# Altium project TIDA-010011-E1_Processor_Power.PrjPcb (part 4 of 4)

## Sheet TIDA-010011-E1_Processor_Power _Pg10.SchDoc: PMIC 3 OUTPUT
size 431 x 279 mm; Date: Not shown in title block; ApprovedBy: Not shown in title block; CheckedBy: Not shown in title block; Author: Not shown in title block; CompanyName: Not shown in title block; DrawnBy: Sreenivasa; Engineer: Not shown in title block; Organization: Not shown in title block; Address1: Not shown in title block; Address2: Not shown in title block; Address3: Not shown in title block; Address4: Not shown in title block; DocumentNumber: 1; Revision: Use project parameter SCH_Rev; SheetNumber: 10; SheetTotal: 12; PageSetup: Record=PageOptions¦CenterHorizontal=True¦CenterVertical=True¦PrintScale=0.62¦XCorrection=1.00¦YCorrection=1.00¦PrintKind=0¦BorderSize=5000000¦LeftOffset=0¦BottomOffset=0¦Orientation=2¦PaperLength=1000¦PaperWidth=1000¦Scale=100¦PaperSource=15¦PrintQuality=600¦MediaType=1¦DitherType=10¦PrintScaleMode=1¦PaperKind=Letter
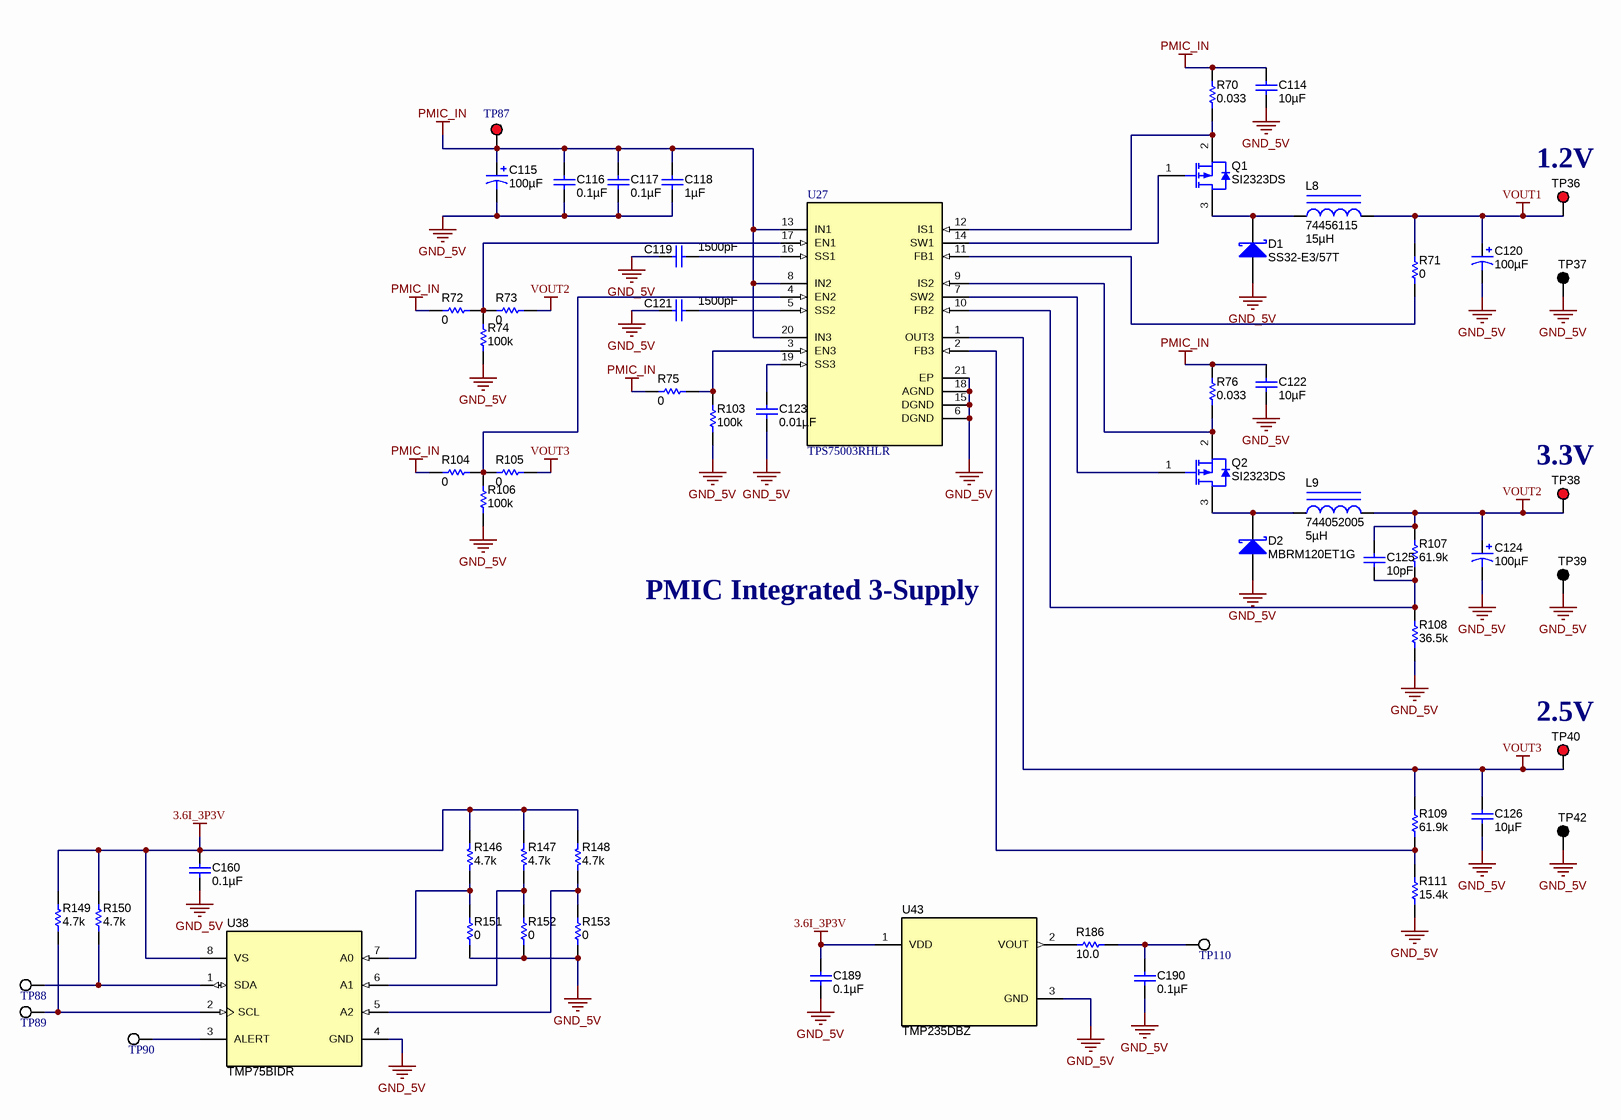
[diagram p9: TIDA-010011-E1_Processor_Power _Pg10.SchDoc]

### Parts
C114  ValueDisplayed: 10µF  [0805_HV]  (hidden comment: CGA4J1X7S1C106K125AC)
C115  ValueDisplayed: 100µF  [7343-20]  (hidden comment: 6TPE100MI)
C116  ValueDisplayed: 0.1µF  [0603]  (hidden comment: C0603C104Z4VACTU)
C117  ValueDisplayed: 0.1µF  [0603]  (hidden comment: C0603C104Z4VACTU)
C118  ValueDisplayed: 1µF  [0603]  (hidden comment: GRM185C80J105KE26D)
C119  ValueDisplayed: 1500pF  [0603]  (hidden comment: GRM188R71H152KA01D)
C120  ValueDisplayed: 100µF  [7343-20]  (hidden comment: 6TPE100MI)
C121  ValueDisplayed: 1500pF  [0603]  (hidden comment: GRM188R71H152KA01D)
C122  ValueDisplayed: 10µF  [0805_HV]  (hidden comment: CGA4J1X7S1C106K125AC)
C123  ValueDisplayed: 0.01µF  [0603]  (hidden comment: GRM188R71E103KA01D)
C124  ValueDisplayed: 100µF  [7343-20]  (hidden comment: 6TPE100MI)
C125  ValueDisplayed: 10pF  [0603]  (hidden comment: C0603C100F5GAC7867)
C126  ValueDisplayed: 10µF  [0805_HV]  (hidden comment: GRM21BR71A106KE51L)
C160  ValueDisplayed: 0.1µF  [0603]  (hidden comment: 06033C104KAT2A)
C189  ValueDisplayed: 0.1µF  [0603]  (hidden comment: 06033C104KAT2A)
C190  ValueDisplayed: 0.1µF  [0603]  (hidden comment: 06033C104KAT2A)
D1  SS32-E3/57T  [SMC]
D2  MBRM120ET1G  [POWERMITE]
L8  74456115  ValueDisplayed: 15µH  [WE-PD4-L]
L9  744052005  ValueDisplayed: 5µH  [WE-TPC-L]
Q1  SI2323DS  [SOT-23]
Q2  SI2323DS  [SOT-23]
R70  ValueDisplayed: 0.033  [1206]  (hidden comment: ERJ-8CWFR033V)
R71  ValueDisplayed: 0  [0603]  (hidden comment: ERJ-3GEY0R00V)
R72  ValueDisplayed: 0  [0603]  (hidden comment: ERJ-3GEY0R00V)
R73  ValueDisplayed: 0  [0603]  (hidden comment: ERJ-3GEY0R00V)
R74  ValueDisplayed: 100k  [0603]  (hidden comment: RC0603FR-07100KL)
R75  ValueDisplayed: 0  [0603]  (hidden comment: ERJ-3GEY0R00V)
R76  ValueDisplayed: 0.033  [1206]  (hidden comment: ERJ-8CWFR033V)
R103  ValueDisplayed: 100k  [0603]  (hidden comment: RC0603FR-07100KL)
R104  ValueDisplayed: 0  [0603]  (hidden comment: ERJ-3GEY0R00V)
R105  ValueDisplayed: 0  [0603]  (hidden comment: ERJ-3GEY0R00V)
R106  ValueDisplayed: 100k  [0603]  (hidden comment: RC0603FR-07100KL)
R107  ValueDisplayed: 61.9k  [0603]  (hidden comment: CRCW060361K9FKEA)
R108  ValueDisplayed: 36.5k  [0603]  (hidden comment: CRCW060336K5FKEA)
R109  ValueDisplayed: 61.9k  [0603]  (hidden comment: CRCW060361K9FKEA)
R111  ValueDisplayed: 15.4k  [0603]  (hidden comment: CRCW060315K4FKEA)
R146  ValueDisplayed: 4.7k  [0603]  (hidden comment: CR0603-JW-472GLF)
R147  ValueDisplayed: 4.7k  [0603]  (hidden comment: CR0603-JW-472GLF)
R148  ValueDisplayed: 4.7k  [0603]  (hidden comment: CR0603-JW-472GLF)
R149  ValueDisplayed: 4.7k  [0603]  (hidden comment: CR0603-JW-472GLF)
R150  ValueDisplayed: 4.7k  [0603]  (hidden comment: CR0603-JW-472GLF)
R151  ValueDisplayed: 0  [0603]  (hidden comment: CRCW06030000Z0EA)
R152  ValueDisplayed: 0  [0603]  (hidden comment: CRCW06030000Z0EA)
R153  ValueDisplayed: 0  [0603]  (hidden comment: CRCW06030000Z0EA)
R186  ValueDisplayed: 10.0  [0603]  (hidden comment: CRCW060310R0FKEAHP)
TP36  5000  [Keystone5000]  (value not drawn)
TP37  5001  [Keystone5001]  (value not drawn)
TP38  5000  [Keystone5000]  (value not drawn)
TP39  5001  [Keystone5001]  (value not drawn)
TP40  5000  [Keystone5000]  (value not drawn)
TP42  5001  [Keystone5001]  (value not drawn)
TP87  5000  [Keystone5000]  (value not drawn)
TP88  5002  [Keystone5002]  (value not drawn)
TP89  5002  [Keystone5002]  (value not drawn)
TP90  5002  [Keystone5002]  (value not drawn)
TP110  5002  [Keystone5002]  (value not drawn)
U27  TPS75003RHLR  [RHL0020A]
U38  TMP75BIDR  [D0008A_N]
U43  TMP235DBZ  [DBZ0003A_N]

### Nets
3.6I_3P3V: C160.2 C189.2 R146.2 R147.2 R148.2 R149.2 R150.2 U38.8(VS) U43.1(VDD)
GND_5V: C114.2 C115.2(-) C116.2 C117.2 C118.2 C119.2 C120.2(-) C121.2 C122.2 C123.2 C124.2(-) C126.2 C160.1 C189.1 C190.1 D1.2(A) D2.2(A) R74.2 R103.2 R106.2 R108.1 R111.1 R151.2 R152.2 R153.2 TP37.1 TP39.1 TP42.1 U27.6(DGND) U27.15(DGND) U27.18(AGND) U27.21(EP) U38.4(GND) U43.3(GND)
PMIC_IN: C114.1 C115.1(+) C116.1 C117.1 C118.1 C122.1 R70.1 R72.2 R75.2 R76.1 R104.2 TP87.1 U27.8(IN2) U27.13(IN1) U27.20(IN3)
VOUT1: C120.1(+) L8.2 R71.1 TP36.1
VOUT2: C124.1(+) C125.1 L9.2 R73.1 R107.2 TP38.1
VOUT3: C126.1 R105.1 R109.2 TP40.1 U27.1(OUT3)
NetC119_1: C119.1 U27.16(SS1)
NetC121_1: C121.1 U27.5(SS2)
NetC123_1: C123.1 U27.19(SS3)
NetC125_2: C125.2 R107.1 R108.2 U27.10(FB2)
NetC190_2: C190.2 R186.1 TP110.1
NetD1_1: D1.1(K) L8.1 Q1.3(D)
NetD2_1: D2.1(K) L9.1 Q2.3(D)
NetQ1_1: Q1.1(G) U27.14(SW1)
NetQ1_2: Q1.2(S) R70.2 U27.12(IS1)
NetQ2_1: Q2.1(G) U27.7(SW2)
NetQ2_2: Q2.2(S) R76.2 U27.9(IS2)
NetR71_2: R71.2 U27.11(FB1)
NetR72_1: R72.1 R73.2 R74.1 U27.17(EN1)
NetR75_1: R75.1 R103.1 U27.3(EN3)
NetR104_1: R104.1 R105.2 R106.1 U27.4(EN2)
NetR109_1: R109.1 R111.2 U27.2(FB3)
NetR146_1: R146.1 R151.1 U38.7(A0)
NetR147_1: R147.1 R152.1 U38.6(A1)
NetR148_1: R148.1 R153.1 U38.5(A2)
NetR149_1: R149.1 TP89.1 U38.2(SCL)
NetR150_1: R150.1 TP88.1 U38.1(SDA)
NetR186_2: R186.2 U43.2(VOUT)
NetTP90_1: TP90.1 U38.3(ALERT)

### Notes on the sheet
- (near TP36) 1.2V
- (near TP38) 3.3V
- PMIC Integrated 3-Supply
- (near TP40) 2.5V

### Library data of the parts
C114 C122 = CGA4J1X7S1C106K125AC: CAP, CERM, 10 µF, 16 V,+/- 10%, X7S, AEC-Q200 Grade 1, 0805; Manufacturer: TDK; Polarized: N; CompType: Capacitor; Value: 10uF; U/M: EA; Cap_F: 0.00001; Tolerance_%: 10; VDC_V: 16; Value2: 16V; TaMin_C: -55; TaMax_C: 125; Cap_Case: 0805; SizeArea_mm2: 2.5; SizeAreaWB_mm2: 6.75; SizeX_mm: 2; SizeY_mm: 1.25; SizeZ_mm: 1.45; AEC Category: Q200; AEC Qualified: Y; AEC Grade: 1
C115 C120 C124 = 6TPE100MI: CAP, Tantalum Polymer, 100 µF, 6.3 V,+/- 20%, 0.018 ohm, 7343-20 SMD; Manufacturer: Panasonic; Polarized: Y; CompType: Capacitor; Value: 100uF; U/M: EA; Cap_F: 0.0001; Tolerance_%: 20; VDC_V: 6.3; Value2: 6.3V; ESR_ohm: 0.018; IRMS_A: 2.8; TaMin_C: -55; TaMax_C: 105; Cap_Case: D; SizeAreaWB_mm2: 58.59; SizeArea_mm2: 31.39; SizeX_mm: 7.3; SizeY_mm: 4.3; SizeZ_mm: 2; AEC Category: Q200; AEC Qualified: N
C116 C117 = C0603C104Z4VACTU: CAP, CERM, 0.1 µF, 16 V,+80/-20%, Y5V, 0603; Manufacturer: Kemet; Polarized: N; CompType: Capacitor; Value: 0.1uF; U/M: EA; Cap_F: 0.0000001; Tolerance_%: 80; VDC_V: 16; Value2: 16V; TaMin_C: -30; TaMax_C: 85; SizeArea_mm2: 1.28; SizeAreaWB_mm2: 4.68; SizeX_mm: 1.6; SizeY_mm: 0.8; SizeZ_mm: 1; AEC Category: Q200; Green_Lifecycle: Not Set; Green_REACh: Incomplete
C118 = GRM185C80J105KE26D: CAP, CERM, 1 µF, 6.3 V,+/- 10%, X6S, 0603; Manufacturer: MuRata; Polarized: N; CompType: Capacitor; Value: 1uF; U/M: EA; Cap_F: 0.000001; Tolerance_%: 10; VDC_V: 6.3; Value2: 6.3V; TaMin_C: -55; TaMax_C: 105; SizeArea_mm2: 1.28; SizeAreaWB_mm2: 4.68; SizeX_mm: 1.6; SizeY_mm: 0.8; SizeZ_mm: 1; AEC Category: Q200; Green_Lifecycle: Active; Green_REACh: Passed
C119 C121 = GRM188R71H152KA01D: CAP, CERM, 1500 pF, 50 V,+/- 10%, X7R, 0603; Manufacturer: MuRata; Polarized: N; CompType: Capacitor; Value: 1500pF; U/M: EA; Cap_F: 0.0000000015; Tolerance_%: 10; VDC_V: 50; Value2: 50V; TaMin_C: -55; TaMax_C: 125; SizeArea_mm2: 1.28; SizeAreaWB_mm2: 4.68; SizeX_mm: 1.6; SizeY_mm: 0.8; SizeZ_mm: 1; AEC Category: Q200; Green_Lifecycle: Active; Green_REACh: Passed
C123 = GRM188R71E103KA01D: CAP, CERM, 0.01 µF, 25 V,+/- 10%, X7R, 0603; Manufacturer: MuRata; Polarized: N; CompType: Capacitor; Value: 0.01uF; U/M: EA; Cap_F: 0.00000001; Tolerance_%: 10; VDC_V: 25; Value2: 25V; TaMin_C: -55; TaMax_C: 125; SizeArea_mm2: 1.28; SizeAreaWB_mm2: 4.68; SizeX_mm: 1.6; SizeY_mm: 0.8; SizeZ_mm: 1; AEC Category: Q200; Green_Lifecycle: Active; Green_REACh: Passed
C125 = C0603C100F5GAC7867: CAP, CERM, 10 pF, 50 V,+/- 1%, C0G/NP0, 0603; Manufacturer: Kemet; Polarized: N; CompType: Capacitor; Value: 10pF; U/M: EA; Cap_F: 0.00000000001; Tolerance_%: 1; VDC_V: 50; Value2: 50V; TaMin_C: -55; TaMax_C: 125; SizeArea_mm2: 1.28; SizeAreaWB_mm2: 4.68; SizeX_mm: 1.6; SizeY_mm: 0.8; AEC Category: Q200; Green_Lifecycle: Active; Green_REACh: Passed
C126 = GRM21BR71A106KE51L: CAP, CERM, 10 µF, 10 V, +/- 10%, X7R, 0805; Manufacturer: MuRata; Polarized: N; CompType: Capacitor; Value: 10uF; U/M: EA; Cap_F: 0.00001; Tolerance_%: 10; ESR_ohm: 0.003; Value1: 0.003 ohm; Value2: 10V; TaMin_C: -55; TaMax_C: 125; Cap_Case: 0805; SizeArea_mm2: 2.5; SizeAreaWB_mm2: 6.75; SizeX_mm: 2; SizeY_mm: 1.25; SizeZ_mm: 1.45; AEC Category: Q200
C160 C189 C190 = 06033C104KAT2A: CAP, CERM, 0.1 µF, 25 V,+/- 10%, X7R, 0603; Manufacturer: AVX; Polarized: N; CompType: Capacitor; Value: 0.1uF; U/M: EA; Cap_F: 0.0000001; Tolerance_%: 10; ESR_ohm: 0.05; Value1: 0.05 ohm; VDC_V: 25; Value2: 25V; TaMin_C: -55; TaMax_C: 125; AEC Category: Q200; SizeArea_mm2: 1.28; SizeAreaWB_mm2: 4.68; SizeX_mm: 1.6; SizeY_mm: 0.8; SizeZ_mm: 1; Green_Lifecycle: Active; Green_REACh: Passed
D1 = SS32-E3/57T: Diode, Schottky, 20 V, 3 A, SMC; Manufacturer: Vishay-Semiconductor; U/M: EA; Vf_V: 0.5; Value: 20V; Value1: 3A; Value2: 0.5V; Io_A: 3; Vr_V: 20; TJmax_C: 125; RJC_CperW: 17; SizeAreaWB_mm2: 83.2686; SizeArea_mm2: 50.5686; SizeX_mm: 8.13; SizeY_mm: 6.22; SizeZ_mm: 2.6; AEC Category: Q101; Green_Lifecycle: Not Set; Green_REACh: Incomplete
D2 = MBRM120ET1G: Diode, Schottky, 20 V, 1 A, POWERMITE; Manufacturer: ON Semiconductor; U/M: EA; Vf_V: 0.53; Value: 20V; Value1: 1A; Value2: 0.53V; Io_A: 1; Vr_V: 20; SizeAreaWB_mm2: 14.945; SizeArea_mm2: 7.995; SizeX_mm: 3.9; SizeY_mm: 2.05; SizeZ_mm: 1.15; AEC Category: Q101; Green_Lifecycle: Active; Green_REACh: Passed
L8 = 74456115: Inductor, Drum Core, Ferrite, 15uH, 2.9A, 0.0432 ohm, SMD; Manufacturer: Wurth Elektronik eiSos; Ind_H: 15.0E-6; Imax_A: 2.9; Irms: 2.9A @ 40C rise; Isat: 3.6A @ 10% inductance drop; DCR_ohm: 0.0432; U/M: EA
L9 = 744052005: Inductor, Shielded Drum Core, Ferrite, 5uH, 1.65A, 0.047 ohm, SMD; Manufacturer: Wurth Elektronik eiSos; Ind_H: 5.0E-6; Imax_A: 1.65; Irms: 1.65A @ 30C rise; Isat: 1.8A @ 35% inductance drop; DCR_ohm: 0.047; U/M: EA
Q1 Q2 = CMP-0000092-2: MOSFET, P-CH, -20 V, -3.7 A, SOT-23; Alternate Manufacturer: None; Manufacturer: Vishay-Siliconix; SizeZ_mm: 1.1; ChType: P; Value2: 12.5 nC; Value1: 0.03; VdsMax_V: -20V; SizeX_mm: 2.5; SizeAreaWB_mm2: 14; SizeY_mm: 3; Vgs_V: -8V; QgTyp_nC: 12.5; Value: -20V; Rdson45_ohm: 0.031; SizeArea_mm2: 7.5; AEC Category: Q101; IdsMax_A: -3.7A; U/M: EA
R70 R76 = ERJ-8CWFR033V: RES, 0.033, 1%, 1 W, AEC-Q200 Grade 0, 1206; Manufacturer: Panasonic; CompType: Resistor; Value: 0.033; Value_Code: R033; Tolerance_%: 1; Value2: 1W; TempCo: 50 ppm/C; SizeArea_mm2: 5.12; SizeX_mm: 3.2; SizeY_mm: 1.6; SizeZ_mm: 1.35; EIA_Code: E96; U/M: EA; AEC Category: Q200; AEC Qualified: Y; AEC Grade: 0; Green_Lifecycle: Not Set; Green_REACh: Incomplete
R71-R73 R75 R104 R105 = ERJ-3GEY0R00V: RES, 0, 5%, 0.1 W, 0603; Manufacturer: Panasonic; CompType: Resistor; Value: 0; Value_Code: 0000; Tolerance_%: 5; Power_W: 0.1; Value2: 0.1W; VDC_V: 50; TempCo: 600 ppm/C; SizeArea_mm2: 1.28; SizeX_mm: 1.6; SizeY_mm: 0.8; SizeZ_mm: 1; EIA_Code: E24; U/M: EA; AEC Category: Q200; Green_Lifecycle: Active; Green_REACh: Passed
R74 R103 R106 = RC0603FR-07100KL: RES, 100 k, 1%, 0.1 W, 0603; Manufacturer: Yageo America; CompType: Resistor; Value: 100k; Res_ohm: 100000; Tolerance_%: 1; Power_W: 0.1; Value2: 0.1W; VDC_V: 150; TempCo: 200 ppm/C; SizeArea_mm2: 1.28; SizeX_mm: 1.6; SizeY_mm: 0.8; EIA_Code: E96; U/M: EA; AEC Category: Q200; Green_Lifecycle: Active; Green_REACh: Passed
R107 R109 = CRCW060361K9FKEA: RES, 61.9 k, 1%, 0.1 W, 0603; Manufacturer: Vishay-Dale; CompType: Resistor; Value: 61.9k; Res_ohm: 61900; Value_Code: 61k9; Tolerance_%: 1; Power_W: 0.1; Value2: 0.1W; VDC_V: 75; TempCo: 100 ppm/C; SizeArea_mm2: 1.28; SizeX_mm: 1.6; SizeY_mm: 0.8; EIA_Code: E96; U/M: EA; AEC Category: Q200; Green_Lifecycle: Active; Green_REACh: Passed
R108 = CRCW060336K5FKEA: RES, 36.5 k, 1%, 0.1 W, 0603; Manufacturer: Vishay-Dale; CompType: Resistor; Value: 36.5k; Res_ohm: 36500; Value_Code: 36k5; Tolerance_%: 1; Power_W: 0.1; Value2: 0.1W; VDC_V: 75; TempCo: 100 ppm/C; SizeArea_mm2: 1.28; SizeX_mm: 1.6; SizeY_mm: 0.8; EIA_Code: E96; U/M: EA; AEC Category: Q200; Green_Lifecycle: Active; Green_REACh: Passed
R111 = CRCW060315K4FKEA: RES, 15.4 k, 1%, 0.1 W, 0603; Manufacturer: Vishay-Dale; CompType: Resistor; Value: 15.4k; Res_ohm: 15400; Value_Code: 15k4; Tolerance_%: 1; Power_W: 0.1; Value2: 0.1W; VDC_V: 75; TempCo: 100 ppm/C; SizeArea_mm2: 1.28; SizeX_mm: 1.6; SizeY_mm: 0.8; EIA_Code: E96; U/M: EA; AEC Category: Q200; Green_Lifecycle: Active; Green_REACh: Passed
R146-R150 = CR0603-JW-472GLF: RES, 4.7 k, 5%, 0.1 W, 0603; Manufacturer: Bourns; CompType: Resistor; Value: 4.7k; Res_ohm: 4700; Value_Code: 4k70; Tolerance_%: 5; Power_W: 0.1; Value2: 0.1W; VDC_V: 50; TempCo: 200 ppm/C; EIA_Code: E24; U/M: EA; AEC Category: Q200; AEC Qualified: N; SizeArea_mm2: 1.28; SizeX_mm: 1.6; SizeY_mm: 0.8; SizeZ_mm: 1; Green_Lifecycle: Active; Green_REACh: Passed
R151-R153 = CRCW06030000Z0EA: RES, 0, 5%, 0.1 W, 0603; Manufacturer: Vishay-Dale; CompType: Resistor; Value: 0; Value_Code: 0000; Tolerance_%: 5; Power_W: 0.1; Value2: 0.1W; VDC_V: 75; TempCo: 200 ppm/C; EIA_Code: E24; U/M: EA; AEC Category: Q200; SizeArea_mm2: 1.28; SizeX_mm: 1.6; SizeY_mm: 0.8; SizeZ_mm: 1; Green_Lifecycle: Active; Green_REACh: Passed
R186 = CRCW060310R0FKEAHP: RES, 10.0, 1%, 0.25 W, 0603; Manufacturer: Vishay-Dale; CompType: Resistor; Value: 10.0; Res_ohm: 10; Value_Code: 10R0; Tolerance_%: 1; Power_W: 0.25; Value2: 0.25W; VDC_V: 75; TempCo: 100 ppm/C; SizeArea_mm2: 1.28; SizeX_mm: 1.6; SizeY_mm: 0.8; EIA_Code: E96; U/M: EA; AEC Category: Q200; Green_Lifecycle: Active; Green_REACh: Passed
TP36 TP38 TP40 = 5000: Test Point, Miniature, Red, TH; Manufacturer: Keystone; CompType: Test Point Loop; U/M: EA
TP37 TP39 TP42 = 5001: Test Point, Miniature, Black, TH; Manufacturer: Keystone; CompType: Test Point Loop; U/M: EA
TP87 = 5000: Test Point, Miniature, Red, TH; Manufacturer: Keystone; CompType: Test Point Loop; ContactFinish: Silver; Green_Lifecycle: Active; Green_REACh: Passed
TP88-TP90 TP110 = 5002: Test Point, Miniature, White, TH; Manufacturer: Keystone; CompType: Test Point Loop; ContactFinish: Silver; Green_Lifecycle: Active; Green_REACh: Passed
U27 = CMP-0037564-2: Integrated Triple Supply Power Management IC for Xilinx (R) Spartan (TM)-3 FPGAs, 2.2 to 6.5 V, -40 to 85 degC, 20-pin QFN (RHL), Green (RoHS & no Sb/Br); Manufacturer: Texas Instruments; SubFamily: DC/DC Controller (External Switch); Vin(Min)(V): 2.2; Vin(Max)(V): 6.5; Topology: Multi-Channel; Regulated Outputs(#): 3
U38 = TMP75BIDR: 1.4V-Capable Temperature Sensor with I2C/SMBus Interface in LM75 Form Factor & Pinout, D0008A (SOIC-8); Manufacturer: Texas Instruments; SymbolCreator: a0411947; SizeArea_mm2: 30.38; SizeAreaWB_mm2: 56.58; SizeX_mm: 4.9; SizeY_mm: 6.2; SizeZ_mm: 1.75; CompType: IC; U/M: EA
U43 = CMP-0013240-2: TMP235DBZ, DBZ0003A (SOP-3); Manufacturer: Texas Instruments; SizeX_mm: 2.5; SizeY_mm: 3; CompType: IC; SizeZ_mm: 1.12; SizeArea_mm2: 7.5; SizeAreaWB_mm2: 14; U/M: EA

## Sheet TIDA-010011-E1_Processor_Power _Pg11.SchDoc: PMIC AM335X
size 431 x 279 mm; Date: Not shown in title block; ApprovedBy: Not shown in title block; CheckedBy: Not shown in title block; Author: Not shown in title block; CompanyName: Not shown in title block; Engineer: Not shown in title block; Organization: Not shown in title block; Address1: Not shown in title block; Address2: Not shown in title block; Address3: Not shown in title block; Address4: Not shown in title block; DocumentNumber: 1; Revision: Use project parameter SCH_Rev; SheetNumber: 11; SheetTotal: 12; PageSetup: Record=PageOptions¦CenterHorizontal=True¦CenterVertical=True¦PrintScale=1.00¦XCorrection=1.00¦YCorrection=1.00¦PrintKind=0¦BorderSize=5000000¦LeftOffset=0¦BottomOffset=0¦Orientation=2¦PaperLength=1000¦PaperWidth=1000¦Scale=100¦PaperSource=15¦PrintQuality=600¦MediaType=1¦DitherType=10¦PaperKind=Letter¦PrintScaleMode=1
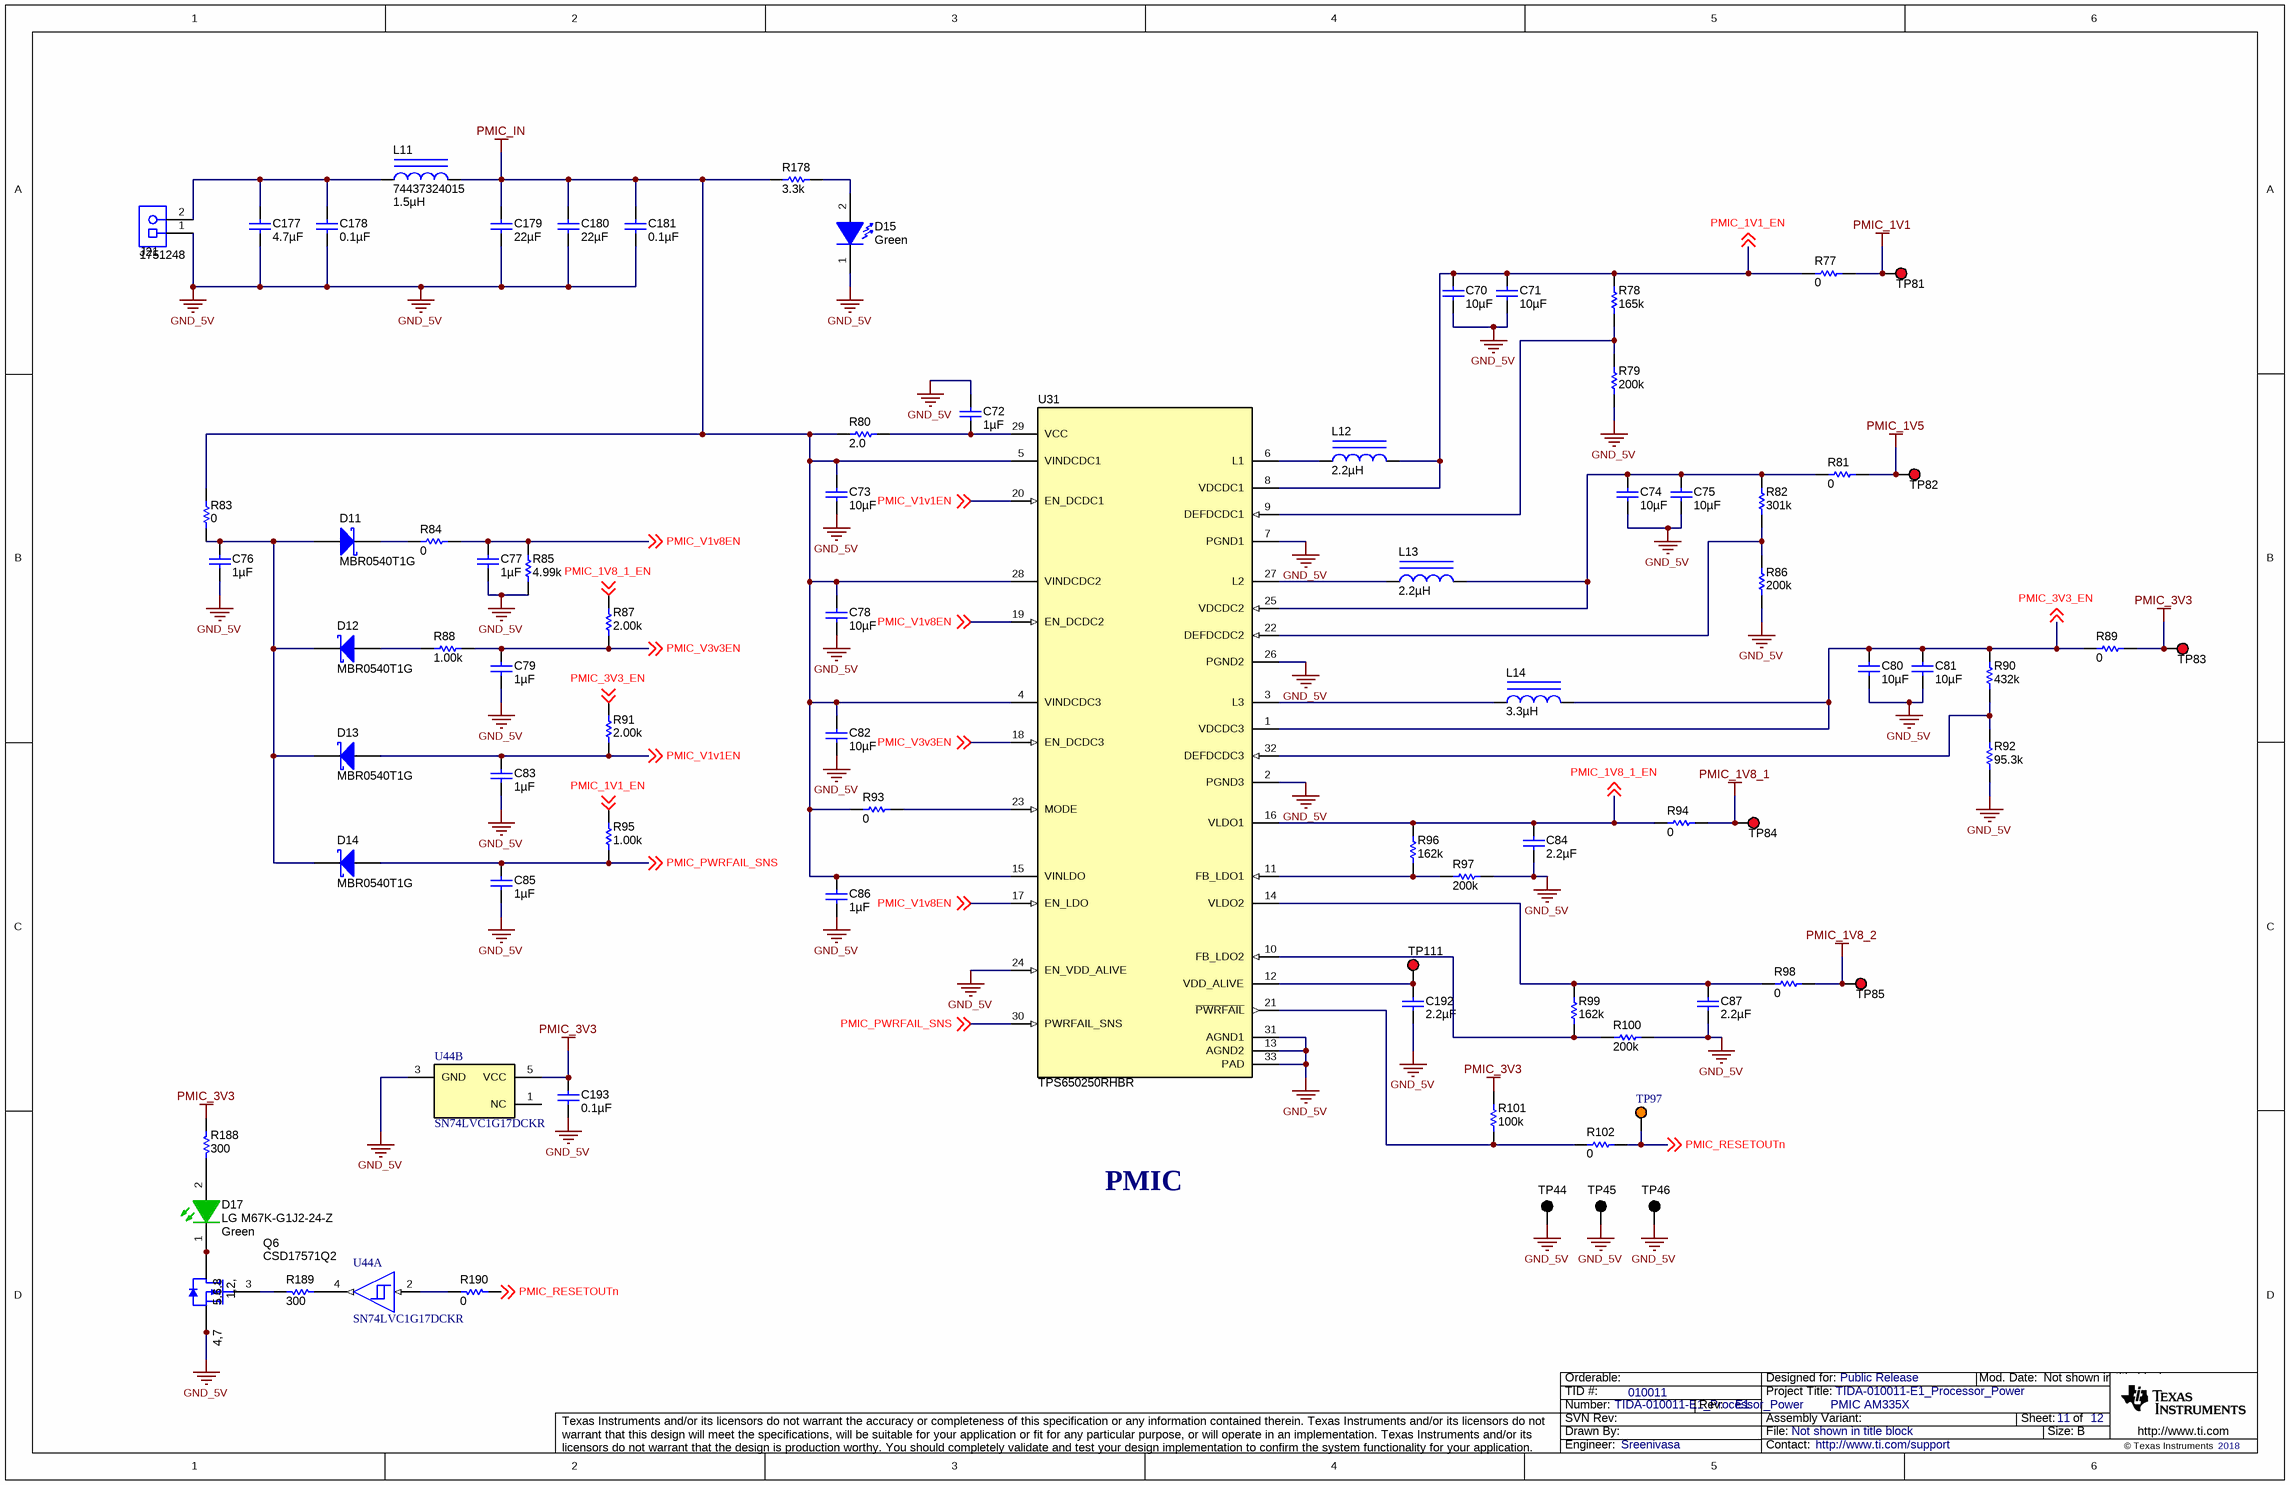
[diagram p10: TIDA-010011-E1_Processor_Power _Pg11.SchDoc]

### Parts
C70  ValueDisplayed: 10µF  [0603]  (hidden comment: C1608X5R1E106M080AC)
C71  ValueDisplayed: 10µF  [0603]  (hidden comment: C1608X5R1E106M080AC)
C72  ValueDisplayed: 1µF  [0603]  (hidden comment: C1608X7R1C105K080AC)
C73  ValueDisplayed: 10µF  [0603]  (hidden comment: C1608X5R1E106M080AC)
C74  ValueDisplayed: 10µF  [0603]  (hidden comment: C1608X5R1E106M080AC)
C75  ValueDisplayed: 10µF  [0603]  (hidden comment: C1608X5R1E106M080AC)
C76  ValueDisplayed: 1µF  [0603]  (hidden comment: C1608X7R1C105K080AC)
C77  ValueDisplayed: 1µF  [0603]  (hidden comment: C1608X7R1C105K080AC)
C78  ValueDisplayed: 10µF  [0603]  (hidden comment: C1608X5R1E106M080AC)
C79  ValueDisplayed: 1µF  [0603]  (hidden comment: C1608X7R1C105K080AC)
C80  ValueDisplayed: 10µF  [0603]  (hidden comment: C1608X5R1E106M080AC)
C81  ValueDisplayed: 10µF  [0603]  (hidden comment: C1608X5R1E106M080AC)
C82  ValueDisplayed: 10µF  [0603]  (hidden comment: C1608X5R1E106M080AC)
C83  ValueDisplayed: 1µF  [0603]  (hidden comment: C1608X7R1C105K080AC)
C84  ValueDisplayed: 2.2µF  [0603]  (hidden comment: GRM188R71A225KE15D)
C85  ValueDisplayed: 1µF  [0603]  (hidden comment: C1608X7R1C105K080AC)
C86  ValueDisplayed: 1µF  [0603]  (hidden comment: C1608X7R1C105K080AC)
C87  ValueDisplayed: 2.2µF  [0603]  (hidden comment: GRM188R71A225KE15D)
C177  ValueDisplayed: 4.7µF  [0603]  (hidden comment: GRM188R61C475KAAJ)
C178  ValueDisplayed: 0.1µF  [0603]  (hidden comment: GRM188R71C104KA01D)
C179  ValueDisplayed: 22µF  [0603]  (hidden comment: GRM188R61A226ME15D)
C180  ValueDisplayed: 22µF  [0603]  (hidden comment: GRM188R61A226ME15D)
C181  ValueDisplayed: 0.1µF  [0603]  (hidden comment: GRM188R71C104KA01D)
C192  ValueDisplayed: 2.2µF  [0603]  (hidden comment: GRM188R71A225KE15D)
C193  ValueDisplayed: 0.1µF  [0603]  (hidden comment: GMK107BJ104KAHT)
D11  MBR0540T1G  [SOD-123]
D12  MBR0540T1G  [SOD-123]
D13  MBR0540T1G  [SOD-123]
D14  MBR0540T1G  [SOD-123]
D15  value Green  [WL-SMCW_GREEN]  (hidden comment: 150060VS75000)
D17  LG M67K-G1J2-24-Z  value Green  [LG_M67K_Green]
J21  1751248  [CONN_1751248]
L11  74437324015  ValueDisplayed: 1.5µH  [IND_WE-LHMI-4020]
L12  ValueDisplayed: 2.2µH  [VLCF4020]  (hidden comment: VLCF4020T-2R2N1R7)
L13  ValueDisplayed: 2.2µH  [VLCF4020]  (hidden comment: VLCF4020T-2R2N1R7)
L14  ValueDisplayed: 3.3µH  [VLCF4020]  (hidden comment: VLCF4020T-3R3N1R5)
Q6  CSD17571Q2  [DQK0006C]
R77  ValueDisplayed: 0  [0402]  (hidden comment: CRCW04020000Z0ED)
R78  ValueDisplayed: 165k  [0402]  (hidden comment: CRCW0402165KFKED)
R79  ValueDisplayed: 200k  [0402]  (hidden comment: CRCW0402200KFKED)
R80  ValueDisplayed: 2.0  [0603]  (hidden comment: CRCW06032R00JNEA)
R81  ValueDisplayed: 0  [0402]  (hidden comment: CRCW04020000Z0ED)
R82  ValueDisplayed: 301k  [0402]  (hidden comment: CRCW0402301KFKED)
R83  ValueDisplayed: 0  [0402]  (hidden comment: CRCW04020000Z0ED)
R84  ValueDisplayed: 0  [0402]  (hidden comment: CRCW04020000Z0ED)
R85  ValueDisplayed: 4.99k  [0402]  (hidden comment: CRCW04024K99FKED)
R86  ValueDisplayed: 200k  [0402]  (hidden comment: CRCW0402200KFKED)
R87  ValueDisplayed: 2.00k  [0402]  (hidden comment: CRCW04022K00FKED)
R88  ValueDisplayed: 1.00k  [0402]  (hidden comment: CRCW04021K00FKED)
R89  ValueDisplayed: 0  [0402]  (hidden comment: CRCW04020000Z0ED)
R90  ValueDisplayed: 432k  [0402]  (hidden comment: CRCW0402432KFKED)
R91  ValueDisplayed: 2.00k  [0402]  (hidden comment: CRCW04022K00FKED)
R92  ValueDisplayed: 95.3k  [0402]  (hidden comment: CRCW040295K3FKED)
R93  ValueDisplayed: 0  [0402]  (hidden comment: CRCW04020000Z0ED)
R94  ValueDisplayed: 0  [0402]  (hidden comment: CRCW04020000Z0ED)
R95  ValueDisplayed: 1.00k  [0402]  (hidden comment: CRCW04021K00FKED)
R96  ValueDisplayed: 162k  [0402]  (hidden comment: CRCW0402162KFKED)
R97  ValueDisplayed: 200k  [0402]  (hidden comment: CRCW0402200KFKED)
R98  ValueDisplayed: 0  [0402]  (hidden comment: CRCW04020000Z0ED)
R99  ValueDisplayed: 162k  [0402]  (hidden comment: CRCW0402162KFKED)
R100  ValueDisplayed: 200k  [0402]  (hidden comment: CRCW0402200KFKED)
R101  ValueDisplayed: 100k  [0402]  (hidden comment: CRCW0402100KJNED)
R102  ValueDisplayed: 0  [0402]  (hidden comment: CRCW04020000Z0ED)
R178  ValueDisplayed: 3.3k  [0402L]  (hidden comment: CRCW04023K30JNED)
R188  ValueDisplayed: 300  [0603]  (hidden comment: CRCW0603300RJNEA)
R189  ValueDisplayed: 300  [0603]  (hidden comment: CRCW0603300RJNEA)
R190  ValueDisplayed: 0  [0603]  (hidden comment: RMCF0603ZT0R00)
TP44  5001  [Keystone5001]  (value not drawn)
TP45  5001  [Keystone5001]  (value not drawn)
TP46  5001  [Keystone5001]  (value not drawn)
TP81  (no value)  [Keystone5000]
TP82  (no value)  [Keystone5000]
TP83  (no value)  [Keystone5000]
TP84  (no value)  [Keystone5000]
TP85  (no value)  [Keystone5000]
TP97  5003  [Keystone5003]  (value not drawn)
TP111  (no value)  [Keystone5000]
U31  TPS650250RHBR  [RHB0032E]
U44  SN74LVC1G17DCKR  [DCK0005A_N]  (parts A,B of 2)

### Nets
GND_5V: C70.2 C71.2 C72.1 C73.2 C74.2 C75.2 C76.2 C77.2 C78.2 C79.2 C80.2 C81.2 C82.2 C83.2 C84.2 C85.2 C86.2 C87.2 C177.2 C178.2 C179.2 C180.2 C181.2 C192.2 C193.2 D15.1(K) J21.1 Q6.4(S) Q6.7(S) R79.1 R85.1 R86.1 R92.1 R97.1 R100.1 TP44.1 TP45.1 TP46.1 U31.2(PGND3) U31.7(PGND1) U31.13(AGND2) U31.24(EN_VDD_ALIVE) U31.26(PGND2) U31.31(AGND1) U31.33(PAD) U44.3(GND)
PMIC_1V1: R77.2 TP81.1
PMIC_1V5: R81.2 TP82.1
PMIC_1V8_1: R94.2 TP84.1
PMIC_1V8_2: R98.2 TP85.1
PMIC_3V3: C193.1 R89.2 R101.2 R188.2 TP83.1 U44.5(VCC)
PMIC_IN: C73.1 C78.1 C82.1 C86.1 C179.1 C180.1 C181.1 L11.2 R80.1 R83.2 R93.1 R178.2 U31.4(VINDCDC3) U31.5(VINDCDC1) U31.15(VINLDO) U31.28(VINDCDC2)
PMIC_1V1_EN: C70.1 C71.1 L12.2 R77.1 R78.2 R95.2 U31.8(VDCDC1) ; off-sheet PMIC_1V1_EN
PMIC_1V8_1_EN: C84.1 R87.2 R94.1 R96.2 U31.16(VLDO1) ; off-sheet PMIC_1V8_1_EN
PMIC_3V3_EN: C80.1 C81.1 L14.2 R89.1 R90.2 R91.2 U31.1(VDCDC3) ; off-sheet PMIC_3V3_EN
PMIC_PWRFAIL_SNS: C85.1 D14.2(A) R95.1 U31.30(PWRFAIL_SNS) ; off-sheet PMIC_PWRFAIL_SNS
PMIC_RESETOUTn: R102.2 R190.1 TP97.1 ; off-sheet PMIC_RESETOUTn
PMIC_V1v1EN: C83.1 D13.2(A) R91.1 U31.20(EN_DCDC1) ; off-sheet PMIC_V1v1EN
PMIC_V1v8EN: C77.1 R84.2 R85.2 U31.17(EN_LDO) U31.19(EN_DCDC2) ; off-sheet PMIC_V1v8EN
PMIC_V3v3EN: C79.1 R87.1 R88.2 U31.18(EN_DCDC3) ; off-sheet PMIC_V3v3EN
NetC72_2: C72.2 R80.2 U31.29(VCC)
NetC74_1: C74.1 C75.1 L13.2 R81.1 R82.2 U31.25(VDCDC2)
NetC76_1: C76.1 D11.2(A) D12.1(K) D13.1(K) D14.1(K) R83.1
NetC87_1: C87.1 R98.1 R99.2 U31.14(VLDO2)
NetC177_1: C177.1 C178.1 J21.2 L11.1
NetC192_1: C192.1 TP111.1 U31.12(VDD_ALIVE)
NetD11_1: D11.1(K) R84.1
NetD12_2: D12.2(A) R88.1
NetD15_2: D15.2(A) R178.1
NetD17_1: D17.1(K) Q6.1(D) Q6.2(D) Q6.5(D) Q6.6(D) Q6.8(D)
NetD17_2: D17.2(A) R188.1
NetL12_1: L12.1 U31.6(L1)
NetL13_1: L13.1 U31.27(L2)
NetL14_1: L14.1 U31.3(L3)
NetQ6_3: Q6.3(G) R189.1
NetR78_1: R78.1 R79.2 U31.9(DEFDCDC1)
NetR82_1: R82.1 R86.2 U31.22(DEFDCDC2)
NetR90_1: R90.1 R92.2 U31.32(DEFDCDC3)
NetR93_2: R93.2 U31.23(MODE)
NetR96_1: R96.1 R97.2 U31.11(FB_LDO1)
NetR99_1: R99.1 R100.2 U31.10(FB_LDO2)
NetR101_1: R101.1 R102.1 U31.21(~{PWRFAIL})
NetR189_2: R189.2 U44.4(Y)
NetR190_2: R190.2 U44.2(A)

Not connected (* = marked no-connect by the designer): U44 1(NC)

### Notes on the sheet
- PMIC

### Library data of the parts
C70 C71 C73-C75 C78 C80-C82 = C1608X5R1E106M080AC: CAP, CERM, 10 µF, 25 V, +/- 20%, X5R, 0603; Manufacturer: TDK; Polarized: N; CompType: Capacitor; Value: 10uF; U/M: EA; Cap_F: 0.00001; Tolerance_%: 20; Value1: Unknown; VDC_V: 25; Value2: 25V; TaMin_C: -55; TaMax_C: 85
C72 C76 C77 C79 C83 C85 C86 = C1608X7R1C105K080AC: CAP, CERM, 1 µF, 16 V,+/- 10%, X7R, 0603; Manufacturer: TDK; Polarized: N; CompType: Capacitor; Value: 1uF; U/M: EA; Cap_F: 0.000001; Tolerance_%: 10; ESR_ohm: 0.0057; Value1: 0.0057 ohm; VDC_V: 16; Value2: 16V; TaMin_C: -55; TaMax_C: 125; SizeArea_mm2: 1.28; SizeAreaWB_mm2: 4.68; SizeX_mm: 1.6; SizeY_mm: 0.8; SizeZ_mm: 1; AEC Category: Q200; Green_Lifecycle: Active; Green_REACh: Passed
C84 C87 C192 = GRM188R71A225KE15D: CAP, CERM, 2.2 µF, 10 V, +/- 10%, X7R, 0603; Manufacturer: MuRata; Polarized: N; CompType: Capacitor; Value: 2.2uF; U/M: EA; Cap_F: 0.0000022; Tolerance_%: 10; ESR_ohm: 0.009; Value1: 0.009 ohm; Value2: 10V; TaMin_C: -55; TaMax_C: 125
C177 = GRM188R61C475KAAJ: CAP, CERM, 4.7 µF, 16 V, +/- 10%, X5R, 0603; Manufacturer: MuRata; Polarized: N; CompType: Capacitor; Value: 4.7uF; U/M: EA; Cap_F: 0.0000047; Tolerance_%: 10; Value1: Unknown; VDC_V: 16; Value2: 16V; TaMin_C: -55; TaMax_C: 85; SizeArea_mm2: 1.28; SizeAreaWB_mm2: 4.68; SizeX_mm: 1.6; SizeY_mm: 0.8; SizeZ_mm: 1; AEC Category: Q200
C178 C181 = GRM188R71C104KA01D: CAP, CERM, 0.1 µF, 16 V, +/- 10%, X7R, 0603; Manufacturer: MuRata; Polarized: N; CompType: Capacitor; Value: 0.1uF; U/M: EA; Cap_F: 0.0000001; Tolerance_%: 10; Value1: Unknown; VDC_V: 16; Value2: 16V; TaMin_C: -55; TaMax_C: 125; SizeArea_mm2: 1.28; SizeAreaWB_mm2: 4.68; SizeX_mm: 1.6; SizeY_mm: 0.8; SizeZ_mm: 1; AEC Category: Q200
C179 C180 = GRM188R61A226ME15D: CAP, CERM, 22 µF, 10 V, +/- 20%, X5R, 0603; Manufacturer: MuRata; Polarized: N; CompType: Capacitor; Value: 22uF; U/M: EA; Cap_F: 0.000022; Tolerance_%: 20; Value1: Unknown; VDC_V: 10; Value2: 10V; TaMin_C: -55; TaMax_C: 85; SizeArea_mm2: 1.28; SizeAreaWB_mm2: 4.68; SizeX_mm: 1.6; SizeY_mm: 0.8; SizeZ_mm: 1; AEC Category: Q200
C193 = 06033C104JAT2A: 0.1µF ±10% 35V Ceramic Capacitor X5R 0603; Manufacturer: Taiyo Yuden; Polarized: N; Value: 0.1uF; U/M: EA; Cap_F: 0.0000001; Tolerance_%: 5; ESR_ohm: 0.05; Value1: 0.05 ohm; VDC_V: 25; Value2: 25V; TempCo: X7R; TaMin_C: -55; TaMax_C: 125; SizeArea_mm2: 1.28; SizeAreaWB_mm2: 4.68; SizeX_mm: 1.6; SizeY_mm: 0.8; SizeZ_mm: 1; AEC Category: Q200
D11-D14 = MBR0540T1G: Diode, Schottky, 40 V, 0.5 A, SOD-123; Manufacturer: ON Semiconductor; U/M: EA; Vf_V: 0.51; Value: 40V; Value1: 0.5A; Value2: 0.51V; Io_A: 0.5; Vr_V: 40; TJmax_C: 150; RJC_CperW: 118; AEC Category: Q101
D15 = 150060VS75000: LED, Green, SMD; Manufacturer: Wurth Elektronik; Type: AlInGaP; Vf_V: 2; Value2: 2V; Io_A: 0.02; Value1: W; U/M: EA
D17 = LG M67K-G1J2-24-Z: LED, Green, SMD; Manufacturer: OSRAM; SymbolCreator: Altium; Type: AlInGaP; Vf_V: 1.8; Value2: 1.8V; Io_A: 0.002; Vr_V: 12; Tjmax_C: 125; Value1: W; Angle: 120; U/M: EA
J21 = 1751248: Conn Term Block, 2POS, 3.5mm, TH; Manufacturer: Phoenix Contact; CompType: Terminal Block; SymbolCreator: a0412235
L11 = 74437324015: Inductor, Shielded Drum Core, Powdered Iron, 1.5uH, 3.8A, 0.0348 ohm, SMD; Manufacturer: Wurth Elektronik eiSos; Ind_H: 1.5E-6; Imax_A: 3.8; Irms: 3.8A @ 40C rise; Isat: 8A @ 20% inductance drop; DCR_ohm: 0.0348; U/M: EA
L12 L13 = VLCF4020T-2R2N1R7: Inductor, Shielded, Ferrite, 2.2 µH, 1.72 A, 0.059 ohm, SMD; Manufacturer: TDK; Value: 2.2uH; Ind_H: 2.2E-6; Imax_A: 1.72; Irms: 2.19A @ 40C rise; Isat: 1.72A @ 30% inductance drop; DCR_ohm: 0.059; Value2: 1.72A; AEC Category: Q200
L14 = VLCF4020T-3R3N1R5: Inductor, Shielded, Ferrite, 3.3 µH, 1.52 A, 0.078 ohm, SMD; Manufacturer: TDK; Value: 3.3uH; Ind_H: 3.3E-6; Imax_A: 1.52; Irms: 1.94A @ 40C rise; Isat: 1.52A @ 30% inductance drop; DCR_ohm: 0.078; Value2: 1.52A; AEC Category: Q200
Q6 = CSD17571Q2: MOSFET, N-CH, 30 V, 22 A, DQK0006C (WSON-6); Manufacturer: Texas Instruments; Alternate Manufacturer: None; U/M: EA; ChType: N; Value: 30V; VdsMax_V: 30; Value1: 0.029 ohm; Rdson45_ohm: 0.029; Value2: 2.4 nC; QgTyp_nC: 2.4; Vgs_V: 20; IdsMax_A: 22; SizeAreaWB_mm2: 9; SizeArea_mm2: 4; SizeX_mm: 2; SizeZ_mm: 0.8; AEC Category: Q101
R77 R81 R83 R84 R89 R93 R94 R98 R102 = CRCW04020000Z0ED: RES, 0, 5%, 0.063 W, 0402; Manufacturer: Vishay-Dale; CompType: Resistor; Value: 0; Value_Code: 0000; Tolerance_%: 5; Power_W: 0.063; Value2: 0.063W; VDC_V: 50; TempCo: 200 ppm/C; EIA_Code: E24; U/M: EA; AEC Category: Q200
R78 = CRCW0402165KFKED: RES, 165 k, 1%, 0.063 W, 0402; Manufacturer: Vishay-Dale; CompType: Resistor; Value: 165k; Res_ohm: 165000; Tolerance_%: 1; Power_W: 0.063; Value2: 0.063W; VDC_V: 50; TempCo: 100 ppm/C; EIA_Code: E96; U/M: EA; AEC Category: Q200
R79 R86 R97 R100 = CRCW0402200KFKED: RES, 200 k, 1%, 0.063 W, 0402; Manufacturer: Vishay-Dale; CompType: Resistor; Value: 200k; Res_ohm: 200000; Tolerance_%: 1; Power_W: 0.063; Value2: 0.063W; VDC_V: 50; TempCo: 100 ppm/C; EIA_Code: E96; U/M: EA; AEC Category: Q200
R80 = CRCW06032R00JNEA: RES, 2.0, 5%, 0.1 W, 0603; Manufacturer: Vishay-Dale; CompType: Resistor; Value: 2.0; Res_ohm: 2; Value_Code: 2R00; Tolerance_%: 5; Power_W: 0.1; Value2: 0.1W; VDC_V: 75; TempCo: 200 ppm/C; EIA_Code: E24; U/M: EA; AEC Category: Q200
R82 = CRCW0402301KFKED: RES, 301 k, 1%, 0.063 W, 0402; Manufacturer: Vishay-Dale; CompType: Resistor; Value: 301k; Res_ohm: 301000; Tolerance_%: 1; Power_W: 0.063; Value2: 0.063W; VDC_V: 50; TempCo: 100 ppm/C; EIA_Code: E96; U/M: EA; AEC Category: Q200
R85 = CRCW04024K99FKED: RES, 4.99 k, 1%, 0.063 W, 0402; Manufacturer: Vishay-Dale; CompType: Resistor; Value: 4.99k; Res_ohm: 4990; Value_Code: 4k99; Tolerance_%: 1; Power_W: 0.063; Value2: 0.063W; VDC_V: 50; TempCo: 100 ppm/C; EIA_Code: E96; U/M: EA; AEC Category: Q200
R87 R91 = CRCW04022K00FKED: RES, 2.00 k, 1%, 0.063 W, 0402; Manufacturer: Vishay-Dale; CompType: Resistor; Value: 2.00k; Res_ohm: 2000; Value_Code: 2k00; Tolerance_%: 1; Power_W: 0.063; Value2: 0.063W; VDC_V: 50; TempCo: 100 ppm/C; EIA_Code: E96; U/M: EA; AEC Category: Q200
R88 R95 = CRCW04021K00FKED: RES, 1.00 k, 1%, 0.063 W, 0402; Manufacturer: Vishay-Dale; CompType: Resistor; Value: 1.00k; Res_ohm: 1000; Value_Code: 1k00; Tolerance_%: 1; Power_W: 0.063; Value2: 0.063W; VDC_V: 50; TempCo: 100 ppm/C; EIA_Code: E96; U/M: EA; AEC Category: Q200
R90 = CRCW0402432KFKED: RES, 432 k, 1%, 0.063 W, 0402; Manufacturer: Vishay-Dale; CompType: Resistor; Value: 432k; Res_ohm: 432000; Tolerance_%: 1; Power_W: 0.063; Value2: 0.063W; VDC_V: 50; TempCo: 100 ppm/C; EIA_Code: E96; U/M: EA; AEC Category: Q200
R92 = CRCW040295K3FKED: RES, 95.3 k, 1%, 0.063 W, 0402; Manufacturer: Vishay-Dale; CompType: Resistor; Value: 95.3k; Res_ohm: 95300; Value_Code: 95k3; Tolerance_%: 1; Power_W: 0.063; Value2: 0.063W; VDC_V: 50; TempCo: 100 ppm/C; EIA_Code: E96; U/M: EA; AEC Category: Q200
R96 R99 = CRCW0402162KFKED: RES, 162 k, 1%, 0.063 W, 0402; Manufacturer: Vishay-Dale; CompType: Resistor; Value: 162k; Res_ohm: 162000; Tolerance_%: 1; Power_W: 0.063; Value2: 0.063W; VDC_V: 50; TempCo: 100 ppm/C; EIA_Code: E96; U/M: EA; AEC Category: Q200
R101 = CRCW0402100KJNED: RES, 100 k, 5%, 0.063 W, 0402; Manufacturer: Vishay-Dale; CompType: Resistor; Value: 100k; Res_ohm: 100000; Tolerance_%: 5; Power_W: 0.063; Value2: 0.063W; VDC_V: 50; TempCo: 200 ppm/C; EIA_Code: E24; U/M: EA; AEC Category: Q200
R178 = CRCW04023K30JNED: RES, 3.3 k, 5%, 0.063 W, 0402; Manufacturer: Vishay-Dale; CompType: Resistor; Value: 3.3k; Res_ohm: 3300; Value_Code: 3k30; Tolerance_%: 5; Power_W: 0.063; Value2: 0.063W; VDC_V: 50; TempCo: 200 ppm/C; EIA_Code: E24; U/M: EA; AEC Category: Q200; SizeArea_mm2: 0.5; SizeX_mm: 1; SizeZ_mm: 0.6
R188 R189 = CRCW0603300RJNEA: RES, 300, 5%, 0.1 W, 0603; Manufacturer: Vishay-Dale; CompType: Resistor; Value: 300; Value_Code: 300R; Tolerance_%: 5; Power_W: 0.1; Value2: 0.1W; VDC_V: 75; TempCo: 200 ppm/C; SizeArea_mm2: 1.28; SizeX_mm: 1.6; SizeY_mm: 0.8; SizeZ_mm: 1; EIA_Code: E24; U/M: EA; AEC Category: Q200
R190 = RMCF0603ZT0R00: RES, 0, 1%, 0.1 W, AEC-Q200 Grade 0, 0603; Manufacturer: Stackpole Electronics Inc; CompType: Resistor; Value: 0; Tolerance_%: 1; Power_W: 0.1; Value2: 0.1W; TempCo: ppm/C; SizeArea_mm2: 1.28; SizeX_mm: 1.6; SizeY_mm: 0.8; U/M: EA; AEC Category: Q200; AEC Qualified: Y
TP44-TP46 = 5001: Test Point, Miniature, Black, TH; Manufacturer: Keystone; CompType: Test Point Loop; ContactFinish: Silver
TP81-TP85 TP111 = 5000: Test Point, Miniature, Red, TH; Manufacturer: Keystone; CompType: Test Point Loop; ContactFinish: Silver
TP97 = 5003: Test Point, Miniature, Orange, TH; Manufacturer: Keystone; CompType: Test Point Loop; ContactFinish: Silver; Green_Lifecycle: Active; Green_REACh: Passed
U31 = TPS650250RHBR: Power Management IC for Li-Ion Powered Systems, RHB0032E; Alternate PartNumber: TPS650250RHBT; Manufacturer: Texas Instruments; SymbolCreator: a0411947; U/M: EA
U44 = CMP-0051704-3: Single Schmitt-Trigger Buffer, DCK0005A, LARGE T&R; Manufacturer: Texas Instruments; tpd @ Nom Voltage(Max)(ns): 11,6.5,5.5,5; Bits(#): 1; VCC(Min)(V): 1.65; F @ Nom Voltage(Max)(Mhz): 150; VCC(Max)(V): 5.5; Input Type: CMOS/TTL; Sub-Family: Non-Inverting Buffer/Driver; Output Type: CMOS; Output Drive (IOL/IOH)(Max)(mA): 32/-32; 3-State Output: No; Logic: True; ICC @ Nom Voltage(Max)(mA): 0.01; Voltage(Nom)(V): 1.8,2.5,3.3,5; Rating: Catalog; Schmitt Trigger: Yes; Technology Family: LVC; AEC Category: Q200; AEC Qualified: N; CompType: IC; SizeAreaWB_mm2: 9.3; SizeArea_mm2: 4.2; SizeX_mm: 2.1; SizeY_mm: 2.0; SizeZ_mm: 1.1

## Sheet TIDA-010011-E1_Processor_Power _EVM_Hardware_Pg11.SchDoc: Hardware
size 431 x 279 mm; Date: Not shown in title block; ApprovedBy: Not shown in title block; CheckedBy: Not shown in title block; Author: Not shown in title block; CompanyName: Not shown in title block; DrawnBy: Sreenivasa; Engineer: Not shown in title block; Organization: Not shown in title block; Address1: Not shown in title block; Address2: Not shown in title block; Address3: Not shown in title block; Address4: Not shown in title block; DocumentNumber: 1; Revision: Use project parameter SCH_Rev; SheetNumber: 12; SheetTotal: 12; PageSetup: Record=PageOptions¦CenterHorizontal=True¦CenterVertical=True¦PrintScale=1.00¦XCorrection=1.00¦YCorrection=1.00¦PrintKind=0¦BorderSize=5000000¦LeftOffset=0¦BottomOffset=0¦Orientation=2¦PaperLength=1000¦PaperWidth=1000¦Scale=100¦PaperSource=15¦PrintQuality=600¦MediaType=1¦DitherType=10¦PaperKind=Letter¦PrintScaleMode=1
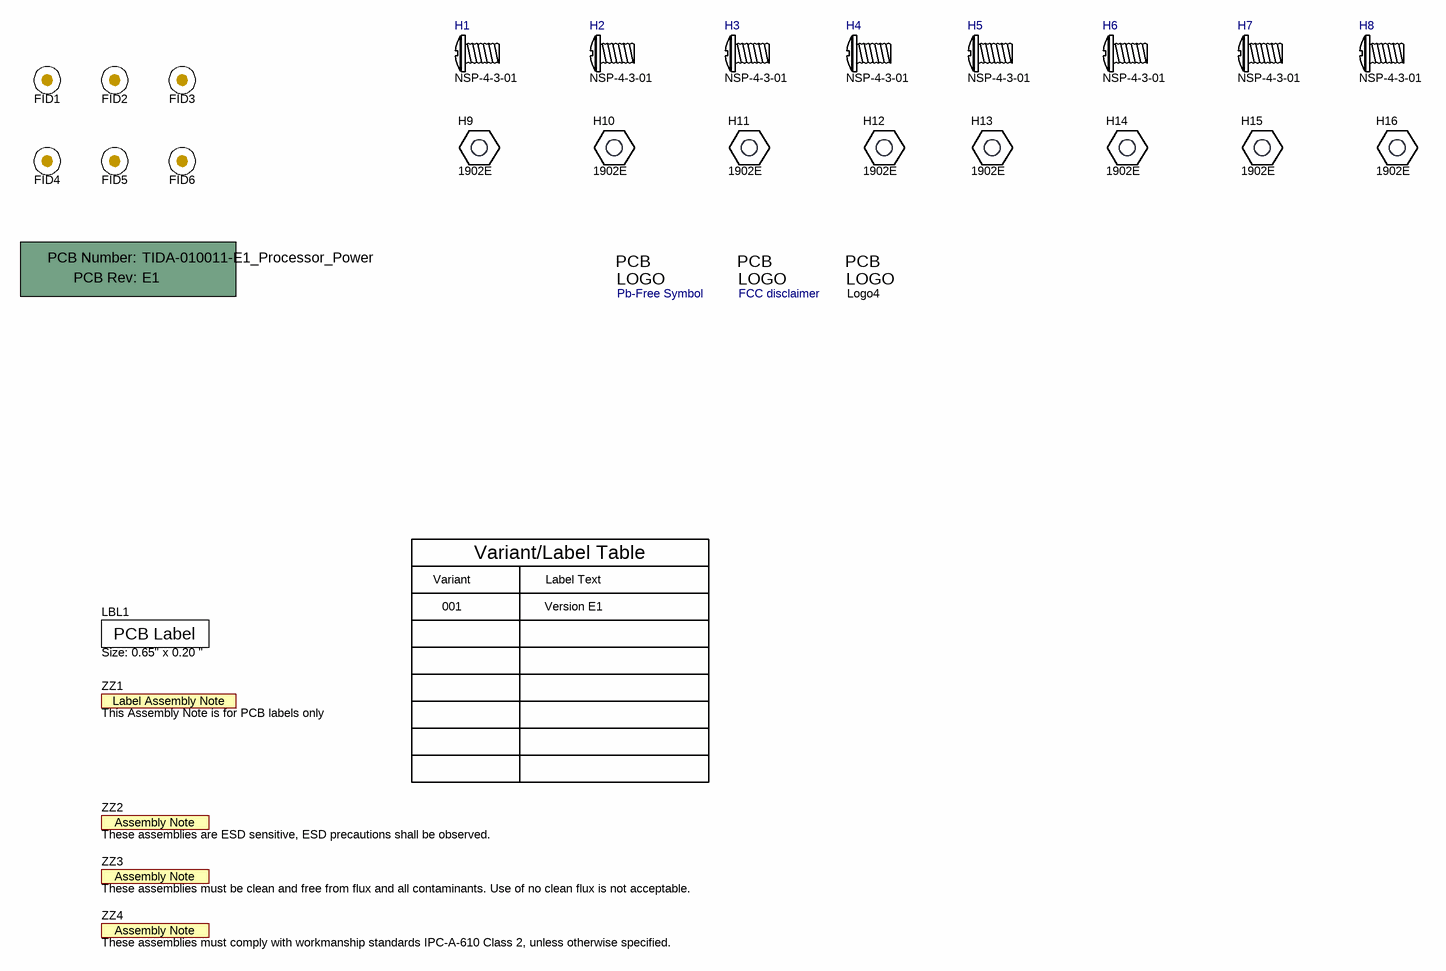
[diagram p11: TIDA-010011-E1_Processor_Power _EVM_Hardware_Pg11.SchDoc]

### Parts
!PCB1  Printed Circuit Board  (value not drawn)  (mechanical)
FID1  Fiducial  [Fiducial10-30]  (value not drawn)
FID2  Fiducial  [Fiducial10-30]  (value not drawn)
FID3  Fiducial  [Fiducial10-30]  (value not drawn)
FID4  Fiducial  [Fiducial10-30]  (value not drawn)
FID5  Fiducial  [Fiducial10-30]  (value not drawn)
FID6  Fiducial  [Fiducial10-30]  (value not drawn)
H1  NSP-4-3-01  [B_F_PMSSS4400025PH]
H2  NSP-4-3-01  [B_F_PMSSS4400025PH]
H3  NSP-4-3-01  [B_F_PMSSS4400025PH]
H4  NSP-4-3-01  [B_F_PMSSS4400025PH]
H5  NSP-4-3-01  [B_F_PMSSS4400025PH]
H6  NSP-4-3-01  [B_F_PMSSS4400025PH]
H7  NSP-4-3-01  [B_F_PMSSS4400025PH]
H8  NSP-4-3-01  [B_F_PMSSS4400025PH]
H9  1902E  [Keystone_1902E]
H10  1902E  [Keystone_1902E]
H11  1902E  [Keystone_1902E]
H12  1902E  [Keystone_1902E]
H13  1902E  [Keystone_1902E]
H14  1902E  [Keystone_1902E]
H15  1902E  [Keystone_1902E]
H16  1902E  [Keystone_1902E]
LBL1  Size: 0.65" x 0.20 "  [Label_650x200]
Logo2  Pb-Free Symbol  [Pb-Free_Overlay_Small]  (no BOM)
Logo3  FCC disclaimer  [FCC_disclaimer_stacked]  (no BOM)
Logo4  ESD Susceptible  [ESD_Overlay_Medium]  (value not drawn)  (no BOM)
ZZ1  This Assembly Note is for PCB labels only  [AssemblyNoteLabel]  (no BOM)
ZZ2  These assemblies are ESD sensitive, ESD precautions shall be observed.  [AssemblyNote]  (no BOM)
ZZ3  These assemblies must be clean and free from flux and all contaminants. Use of no clean flux is not acceptable.  [AssemblyNote]  (no BOM)
ZZ4  These assemblies must comply with workmanship standards IPC-A-610 Class 2, unless otherwise specified.  [AssemblyNote]  (no BOM)

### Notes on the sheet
- Variant
- Variant/Label Table
- Label Text
- 001
- Version E1

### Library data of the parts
!PCB1 = PCB: Manufacturer: Any; PartNumber: TIDA-010011-E1_Processor_Power; SymbolCreator: a0412235
FID1-FID6 = Fiducial: Fiducial mark.  There is nothing to buy or mount.; SymbolCreator: codlsc
H1-H8 = PMSSS 440 0025 PH: MACHINE SCREW PAN PHILLIPS 4-40; Manufacturer: Essentra Components; CompType: Standoff; SymbolCreator: a0412235
H9-H16 = 1902E: Standoff, Hex, 1"L #4-40 Nylon; Manufacturer: Keystone; CompType: Hardware; SymbolCreator: a0412235
LBL1 = THT-14-423-10: Thermal Transfer Printable Labels, 0.650" W x 0.200" H - 10,000 per roll; Manufacturer: Brady; SymbolCreator: a0412235; CompType: Label
Logo2 = Pb-Free: SymbolCreator: a0412235
Logo3 = FCC_disclaimer: SymbolCreator: codlsc
Logo4 = ESD_Susceptible: ESD Susceptible Symbol; SymbolCreator: a0412235
ZZ1 = AssemblyNoteLabel: SymbolCreator: a0412235
ZZ2-ZZ4 = AssemblyNote: SymbolCreator: codlsc

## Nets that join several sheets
3.6I_3P3V: TIDA-010011-E1_Processor_Power _Pg7 (C148.1 U26.2), TIDA-010011-E1_Processor_Power _Pg8 (18 pins), TIDA-010011-E1_Processor_Power _Pg10 (9 pins)
5V_Efuse_Out: TIDA-010011-E1_Processor_Power _Pg7 (11 pins), TIDA-010011-E1_Processor_Power _Pg8 (R56.1 R180.2), TIDA-010011-E1_Processor_Power _Pg9 (R181.1 R182.2)
24V_S: TIDA-010011-E1_Processor_Power _Pg5 (8 pins), TIDA-010011-E1_Processor_Power _Pg6 (R166.2)
GND: TIDA-010011-E1_Processor_Power _Pg3 (48 pins), TIDA-010011-E1_Processor_Power _Pg4 (65 pins), TIDA-010011-E1_Processor_Power _Pg5 (57 pins), TIDA-010011-E1_Processor_Power _Pg6 (61 pins)
GND_5V: TIDA-010011-E1_Processor_Power _Pg7 (52 pins), TIDA-010011-E1_Processor_Power _Pg8 (61 pins), TIDA-010011-E1_Processor_Power _Pg9 (25 pins), TIDA-010011-E1_Processor_Power _Pg10 (34 pins), TIDA-010011-E1_Processor_Power _Pg11 (46 pins)
PM_2.5V_Out: TIDA-010011-E1_Processor_Power _Pg8 (19 pins), TIDA-010011-E1_Processor_Power _Pg9 (R171.1)
PM_3.6V_Out: TIDA-010011-E1_Processor_Power _Pg7 (16 pins), TIDA-010011-E1_Processor_Power _Pg8 (7 pins)
PMIC_IN: TIDA-010011-E1_Processor_Power _Pg10 (15 pins), TIDA-010011-E1_Processor_Power _Pg11 (16 pins)
VCC_1.8V_2A: TIDA-010011-E1_Processor_Power _Pg8 (R128.2), TIDA-010011-E1_Processor_Power _Pg9 (9 pins)

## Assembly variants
001: not fitted D8 FID1 FID2 FID3 FID4 FID5 FID6 R4 R27 R43 R44 R50 R51 R57 R59 R60 R62 R63 R65 R66 R67 R72 R104 R114 R148 R151 R152 R159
